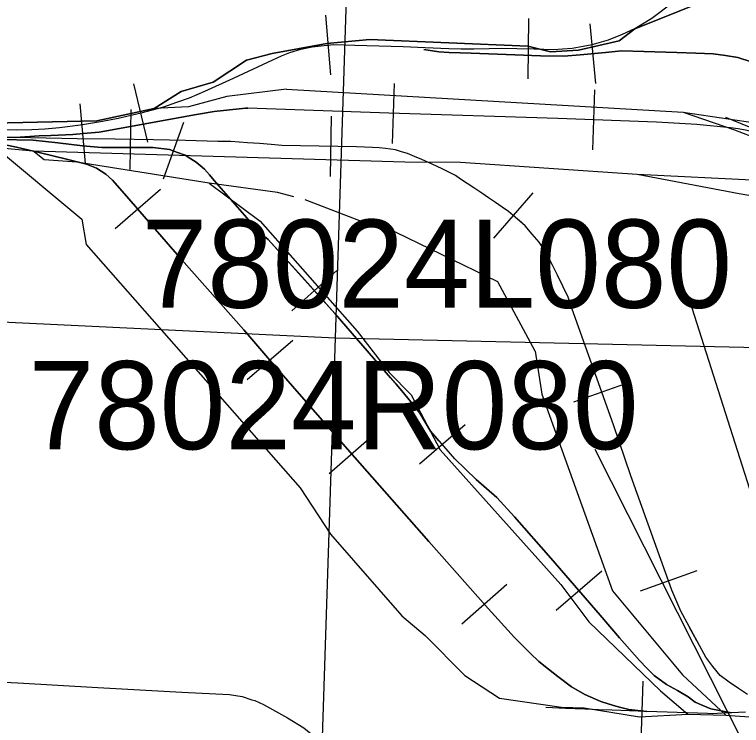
# Model space of a CAD drawing. Extents: x -132.8 to -73.3, y -60 to -26.
# Drawn here: x -124.287 to -123.38, y -50.739 to -49.852 of the extents above; entities that cross this region are included whole.
import ezdxf

# ---------------------------------------------------------------- set-up
doc = ezdxf.new("R2010")
doc.units = 0
for name, color, linetype in [('tdCoCityStreetMajor', 7, 'Continuous'), ('tdCoRRCL', 7, 'Continuous'), ('tdCoSectLine', 7, 'Continuous'), ('tdCoStrucPriMaintName', 7, 'Continuous')]:
    doc.layers.add(name, color=color, linetype=linetype)

msp = doc.modelspace()

# ---------------------------------------------------------------- linework, layer by layer
at = {"layer": 'tdCoCityStreetMajor'}
msp.add_lwpolyline([(-124.81065, -50.63822), (-124.79515, -50.64818), (-124.78487, -50.6531), (-124.78384, -50.6536), (-124.76904, -50.65769), (-124.75304, -50.65973), (-124.7185, -50.66154), (-124.65337, -50.66479), (-124.54813, -50.67104), (-124.45891, -50.67598), (-124.36561, -50.68127), (-124.28295, -50.68524), (-124.18296, -50.69102), (-124.07817, -50.69703), (-124.01897, -50.70004), (-124.00321, -50.70257), (-123.99084, -50.70644), (-123.98744, -50.7075), (-123.97662, -50.71255), (-123.9463, -50.72892), (-123.9262, -50.74143), (-123.91237, -50.75262), (-123.89428, -50.77269)], dxfattribs=at)
at = {"layer": 'tdCoRRCL'}
for p, q in [((-123.8924, -49.92708), (-123.89889, -49.85237)), ((-123.64625, -49.93176), (-123.64535, -49.85677)), ((-123.56938, -49.86305), (-123.56253, -49.93773)), ((-123.84368, -49.88279), (-123.89747, -49.88769)), ((-123.89747, -49.88769), (-123.84368, -49.88279)), ((-123.6466, -49.89112), (-123.84368, -49.88279)), ((-123.84368, -49.88279), (-123.6466, -49.89112)), ((-123.61837, -49.89816), (-123.6466, -49.89112)), ((-123.6466, -49.89112), (-123.61837, -49.89816)), ((-123.99746, -49.90873), (-124.03921, -49.93604)), ((-124.03921, -49.93604), (-123.99746, -49.90873)), ((-124.12083, -50.01086), (-124.13823, -49.93791)), ((-123.8135, -49.93758), (-123.81583, -50.01254)), ((-123.94789, -49.94475), (-123.45303, -49.97349)), ((-123.56344, -49.94558), (-123.56616, -50.02053)), ((-124.19849, -50.03762), (-124.20508, -49.96291)), ((-124.11267, -49.96882), (-124.1841, -49.98431)), ((-124.1841, -49.98431), (-124.11267, -49.96882)), ((-124.14191, -49.96999), (-124.14297, -50.04498)), ((-123.45303, -49.97349), (-123.36341, -49.98689)), ((-123.45303, -49.97349), (-123.38889, -49.99569)), ((-123.89205, -49.97861), (-123.89332, -50.0536)), ((-124.07616, -49.98652), (-124.10157, -50.05709)), ((-123.38889, -49.99569), (-123.33107, -50.01771)), ((-124.31123, -50.01726), (-124.26399, -50.02165)), ((-124.26399, -50.02165), (-123.80031, -50.03539)), ((-123.80031, -50.03539), (-123.73086, -50.03563)), ((-123.73086, -50.03563), (-123.51029, -50.05088)), ((-123.51029, -50.05088), (-123.22339, -50.06471)), ((-123.51029, -50.05088), (-123.38306, -50.07473)), ((-123.95914, -50.07382), (-124.04408, -50.06213)), ((-124.10476, -50.07007), (-124.16146, -50.11916)), ((-123.93877, -50.07909), (-123.95914, -50.07382)), ((-123.64058, -50.07394), (-123.68979, -50.13054)), ((-123.85433, -50.1097), (-123.92465, -50.08262)), ((-123.88514, -50.17114), (-123.94091, -50.22128)), ((-123.94002, -50.25836), (-123.99697, -50.30717)), ((-123.63758, -50.27158), (-123.62951, -50.32543)), ((-123.51935, -50.31012), (-123.59002, -50.33526)), ((-123.72507, -50.36358), (-123.78178, -50.41267)), ((-123.83809, -50.37519), (-123.89436, -50.42478)), ((-123.5545, -50.54596), (-123.61125, -50.59499)), ((-123.43613, -50.54579), (-123.50675, -50.57104)), ((-123.6728, -50.56275), (-123.72907, -50.61234)), ((-123.50316, -50.6834), (-123.50567, -50.75836)), ((-123.44736, -50.72464), (-123.40004, -50.72588)), ((-123.40004, -50.72588), (-123.31179, -50.73135))]:
    msp.add_line(p, q, dxfattribs=at)
for points in [[(-124.31163, -49.99527), (-124.28437, -49.99554), (-124.26524, -49.99501), (-124.24898, -49.99423), (-124.23063, -49.99239), (-124.20468, -49.98925), (-124.17716, -49.98479), (-124.15776, -49.98112), (-124.12918, -49.9743), (-124.10061, -49.9667), (-124.08436, -49.96093), (-124.06889, -49.95543), (-124.04949, -49.9473), (-124.01384, -49.93105), (-123.96482, -49.90798), (-123.95381, -49.903), (-123.94359, -49.89907), (-123.9297, -49.89487), (-123.9158, -49.89199), (-123.9006, -49.89016), (-123.88854, -49.88911), (-123.86259, -49.88989), (-123.80229, -49.89173), (-123.77475, -49.89274), (-123.74541, -49.89383), (-123.72994, -49.89461), (-123.71395, -49.89461), (-123.69508, -49.89383), (-123.67988, -49.89356), (-123.66048, -49.89409), (-123.63872, -49.89435), (-123.61486, -49.89514), (-123.60359, -49.89461), (-123.59153, -49.89356), (-123.57764, -49.8912), (-123.56663, -49.88885), (-123.54618, -49.88334), (-123.52862, -49.87626), (-123.51315, -49.86892), (-123.49218, -49.85634), (-123.46492, -49.83563)], [(-124.31163, -49.99527), (-124.28437, -49.99554), (-124.26524, -49.99501), (-124.24898, -49.99423), (-124.23063, -49.99239), (-124.20468, -49.98925), (-124.17716, -49.98479), (-124.15776, -49.98112), (-124.12918, -49.9743), (-124.10061, -49.9667), (-124.08436, -49.96093), (-124.06889, -49.95543), (-124.04949, -49.9473), (-124.01384, -49.93105), (-123.96482, -49.90798), (-123.95381, -49.903), (-123.94359, -49.89907), (-123.9297, -49.89487), (-123.9158, -49.89199), (-123.9006, -49.89016), (-123.88854, -49.88911), (-123.86259, -49.88989), (-123.80229, -49.89173), (-123.77475, -49.89274), (-123.74541, -49.89383), (-123.72994, -49.89461), (-123.71395, -49.89461), (-123.69508, -49.89383), (-123.67988, -49.89356), (-123.66048, -49.89409), (-123.63872, -49.89435), (-123.61486, -49.89514), (-123.60359, -49.89461), (-123.59153, -49.89356), (-123.57764, -49.8912), (-123.56663, -49.88885), (-123.54618, -49.88334), (-123.52862, -49.87626), (-123.51315, -49.86892), (-123.49218, -49.85634), (-123.46492, -49.83563)], [(-123.43529, -49.83828), (-123.51345, -49.86936), (-123.53279, -49.88463)], [(-123.53279, -49.88463), (-123.51345, -49.86936), (-123.43529, -49.83828)], [(-123.53279, -49.88463), (-123.58359, -49.89592), (-123.61837, -49.89816)], [(-123.61837, -49.89816), (-123.58359, -49.89592), (-123.53279, -49.88463)], [(-123.89747, -49.88769), (-123.96566, -49.9001), (-123.99746, -49.90873)], [(-123.99746, -49.90873), (-123.96566, -49.9001), (-123.89747, -49.88769)], [(-123.77636, -49.89529), (-123.75773, -49.89815), (-123.74489, -49.89894), (-123.71762, -49.89999), (-123.6631, -49.90182), (-123.63112, -49.90313), (-123.60202, -49.90366), (-123.58157, -49.90182), (-123.55012, -49.89894), (-123.52993, -49.8971), (-123.50214, -49.89763), (-123.46099, -49.8992), (-123.43713, -49.89972), (-123.41564, -49.90077), (-123.40043, -49.90261), (-123.38497, -49.90523), (-123.36845, -49.91047)], [(-123.36845, -49.91047), (-123.38497, -49.90523), (-123.40043, -49.90261), (-123.41564, -49.90077), (-123.43713, -49.89972), (-123.46099, -49.8992), (-123.50214, -49.89763), (-123.52993, -49.8971), (-123.55012, -49.89894), (-123.58157, -49.90182), (-123.60202, -49.90366), (-123.63112, -49.90313), (-123.6631, -49.90182), (-123.71762, -49.89999), (-123.74489, -49.89894), (-123.75773, -49.89815), (-123.77636, -49.89529)], [(-124.03921, -49.93604), (-124.07897, -49.94762), (-124.11267, -49.96882)], [(-124.11267, -49.96882), (-124.07897, -49.94762), (-124.03921, -49.93604)], [(-123.94789, -49.94475), (-124.02231, -49.95384), (-124.07, -49.96679), (-124.11267, -49.96882)], [(-123.99614, -49.96832), (-123.99877, -49.9686), (-124.03783, -49.9728), (-124.05985, -49.9762), (-124.08973, -49.98171), (-124.16051, -49.99455), (-124.18148, -49.99822), (-124.19642, -49.9998), (-124.21425, -50.00137), (-124.24151, -50.00268), (-124.25619, -50.00294), (-124.28582, -50.00517), (-124.31166, -50.00452), (-124.39608, -50.00385), (-124.4516, -50.00305)], [(-124.4516, -50.00305), (-124.39608, -50.00385), (-124.31166, -50.00452), (-124.28582, -50.00517), (-124.25619, -50.00294), (-124.24151, -50.00268), (-124.21425, -50.00137), (-124.19642, -49.9998), (-124.18148, -49.99822), (-124.16051, -49.99455), (-124.08973, -49.98171), (-124.05985, -49.9762), (-124.03783, -49.9728), (-123.99877, -49.9686), (-123.99614, -49.96832)], [(-123.07285, -50.0604), (-123.12281, -50.05616), (-123.15614, -50.04919), (-123.2223, -50.03535), (-123.22552, -50.03467), (-123.26481, -50.0259), (-123.30142, -50.018), (-123.33709, -50.00708), (-123.34774, -50.00384), (-123.37315, -49.99612), (-123.38466, -49.9944), (-123.39412, -49.99298), (-123.43606, -49.98878), (-123.48639, -49.9859), (-123.60933, -49.98145), (-123.8201, -49.97489), (-123.99614, -49.96832)], [(-123.07285, -50.0604), (-123.12281, -50.05616), (-123.15614, -50.04919), (-123.2223, -50.03535), (-123.22552, -50.03467), (-123.26481, -50.0259), (-123.30142, -50.018), (-123.33709, -50.00708), (-123.34774, -50.00384), (-123.37315, -49.99612), (-123.38466, -49.9944), (-123.39412, -49.99298), (-123.43606, -49.98878), (-123.48639, -49.9859), (-123.60933, -49.98145), (-123.8201, -49.97489), (-123.99614, -49.96832)], [(-124.1841, -49.98431), (-124.4431, -49.99014), (-124.50308, -49.99014)], [(-124.50308, -49.99014), (-124.4431, -49.99014), (-124.1841, -49.98431)], [(-123.32035, -50.01265), (-123.39995, -49.98026)], [(-124.34646, -50.00681), (-124.32956, -50.00919), (-124.31265, -50.01157), (-124.29863, -50.01432), (-124.2846, -50.01707), (-124.27045, -50.02035), (-124.25629, -50.02363), (-124.22038, -50.03254), (-124.19705, -50.03831), (-124.18473, -50.04329), (-124.17319, -50.05089), (-124.16454, -50.05823), (-124.14986, -50.07527), (-124.07882, -50.15732), (-124.00097, -50.24487), (-123.96849, -50.28276)], [(-123.96849, -50.28276), (-124.00097, -50.24487), (-124.07882, -50.15732), (-124.14986, -50.07527), (-124.16454, -50.05823), (-124.17319, -50.05089), (-124.18473, -50.04329), (-124.19705, -50.03831), (-124.22038, -50.03254), (-124.25629, -50.02363), (-124.27045, -50.02035), (-124.2846, -50.01707), (-124.29863, -50.01432), (-124.31265, -50.01157), (-124.32956, -50.00919), (-124.34646, -50.00681)], [(-124.30497, -50.00757), (-124.26348, -50.00833), (-124.23271, -50.01191), (-124.20194, -50.01549), (-124.17804, -50.01773), (-124.16087, -50.0176), (-124.1437, -50.01747), (-124.12876, -50.0176), (-124.11382, -50.01773), (-124.09363, -50.02009), (-124.0838, -50.02363), (-124.07397, -50.02717), (-124.06716, -50.03149), (-124.06034, -50.03582), (-124.05523, -50.04014), (-124.05012, -50.04447), (-124.04396, -50.05154), (-124.0378, -50.05862), (-124.00031, -50.10188), (-123.99507, -50.10791), (-123.98983, -50.11393), (-123.98354, -50.12036), (-123.97724, -50.12678), (-123.97057, -50.1322), (-123.92882, -50.17864), (-123.88707, -50.22508), (-123.8526, -50.26493), (-123.81812, -50.30477), (-123.81105, -50.3129), (-123.80397, -50.32103), (-123.79263, -50.33499), (-123.78129, -50.34895), (-123.77467, -50.36015), (-123.76806, -50.37136), (-123.75759, -50.38332), (-123.73789, -50.40608), (-123.71125, -50.43174), (-123.68548, -50.45419), (-123.66346, -50.47831), (-123.61811, -50.52969), (-123.55651, -50.60099), (-123.53239, -50.62904), (-123.50749, -50.65761), (-123.49857, -50.66705), (-123.48927, -50.67636), (-123.47387, -50.68726), (-123.46033, -50.69511), (-123.4468, -50.70297), (-123.43805, -50.70967), (-123.42835, -50.71374), (-123.41865, -50.7178), (-123.39271, -50.72278)], [(-123.39271, -50.72278), (-123.41865, -50.7178), (-123.42835, -50.71374), (-123.43805, -50.70967), (-123.4468, -50.70297), (-123.46033, -50.69511), (-123.47387, -50.68726), (-123.48927, -50.67636), (-123.49857, -50.66705), (-123.50749, -50.65761), (-123.53239, -50.62904), (-123.55651, -50.60099), (-123.61811, -50.52969), (-123.66346, -50.47831), (-123.68548, -50.45419), (-123.71125, -50.43174), (-123.73789, -50.40608), (-123.75759, -50.38332), (-123.76806, -50.37136), (-123.77467, -50.36015), (-123.78129, -50.34895), (-123.79263, -50.33499), (-123.80397, -50.32103), (-123.81105, -50.3129), (-123.81812, -50.30477), (-123.8526, -50.26493), (-123.88707, -50.22508), (-123.92882, -50.17864), (-123.97057, -50.1322), (-123.97724, -50.12678), (-123.98354, -50.12036), (-123.98983, -50.11393), (-123.99507, -50.10791), (-124.00031, -50.10188), (-124.0378, -50.05862), (-124.04396, -50.05154), (-124.05012, -50.04447), (-124.05523, -50.04014), (-124.06034, -50.03582), (-124.06716, -50.03149), (-124.07397, -50.02717), (-124.0838, -50.02363), (-124.09363, -50.02009), (-124.11382, -50.01773), (-124.12876, -50.0176), (-124.1437, -50.01747), (-124.16087, -50.0176), (-124.17804, -50.01773), (-124.20194, -50.01549), (-124.23271, -50.01191), (-124.26348, -50.00833), (-124.30497, -50.00757)], [(-123.37269, -50.70002), (-123.38419, -50.69262), (-123.39554, -50.68441), (-123.40688, -50.6762), (-123.41592, -50.66486), (-123.42497, -50.65352), (-123.45588, -50.5959), (-123.4674, -50.56972), (-123.5184, -50.42708), (-123.54011, -50.36365), (-123.59144, -50.21936), (-123.59666, -50.20421), (-123.60326, -50.19043), (-123.60987, -50.17664), (-123.61644, -50.16366), (-123.62302, -50.15067), (-123.62779, -50.14312), (-123.63256, -50.13556), (-123.64126, -50.12547), (-123.64995, -50.11539), (-123.65479, -50.11123), (-123.65964, -50.10706), (-123.66517, -50.10225), (-123.6707, -50.09744), (-123.67892, -50.09186), (-123.68714, -50.08627), (-123.69569, -50.08036), (-123.70424, -50.07444), (-123.71426, -50.06782), (-123.73058, -50.05688), (-123.73688, -50.05257), (-123.74519, -50.04842), (-123.75349, -50.04426), (-123.76629, -50.03831), (-123.77909, -50.03236), (-123.78796, -50.02877), (-123.79683, -50.02518), (-123.80424, -50.02282), (-123.81165, -50.02047), (-123.81793, -50.01957), (-123.82422, -50.01867), (-123.8323, -50.018), (-123.84038, -50.01732), (-123.85049, -50.01699), (-123.86059, -50.01665), (-123.90707, -50.01586), (-123.95354, -50.01508), (-123.96703, -50.01376), (-123.98121, -50.01238), (-123.9962, -50.01171), (-124.01708, -50.01014), (-124.03347, -50.00991), (-124.07355, -50.0089), (-124.11363, -50.00789), (-124.16123, -50.00722), (-124.20883, -50.00654), (-124.24732, -50.00586), (-124.28582, -50.00517)], [(-123.37269, -50.70002), (-123.38419, -50.69262), (-123.39554, -50.68441), (-123.40688, -50.6762), (-123.41592, -50.66486), (-123.42497, -50.65352), (-123.45588, -50.5959), (-123.4674, -50.56972), (-123.5184, -50.42708), (-123.54011, -50.36365), (-123.59144, -50.21936), (-123.59666, -50.20421), (-123.60326, -50.19043), (-123.60987, -50.17664), (-123.61644, -50.16366), (-123.62302, -50.15067), (-123.62779, -50.14312), (-123.63256, -50.13556), (-123.64126, -50.12547), (-123.64995, -50.11539), (-123.65479, -50.11123), (-123.65964, -50.10706), (-123.66517, -50.10225), (-123.6707, -50.09744), (-123.67892, -50.09186), (-123.68714, -50.08627), (-123.69569, -50.08036), (-123.70424, -50.07444), (-123.71426, -50.06782), (-123.73058, -50.05688), (-123.73688, -50.05257), (-123.74519, -50.04842), (-123.75349, -50.04426), (-123.76629, -50.03831), (-123.77909, -50.03236), (-123.78796, -50.02877), (-123.79683, -50.02518), (-123.80424, -50.02282), (-123.81165, -50.02047), (-123.81793, -50.01957), (-123.82422, -50.01867), (-123.8323, -50.018), (-123.84038, -50.01732), (-123.85049, -50.01699), (-123.86059, -50.01665), (-123.90707, -50.01586), (-123.95354, -50.01508), (-123.96703, -50.01376), (-123.98121, -50.01238), (-123.9962, -50.01171), (-124.01708, -50.01014), (-124.03347, -50.00991), (-124.07355, -50.0089), (-124.11363, -50.00789), (-124.16123, -50.00722), (-124.20883, -50.00654), (-124.24732, -50.00586), (-124.28582, -50.00517)], [(-124.31123, -50.01726), (-124.20308, -50.10687), (-124.19759, -50.13857), (-123.93087, -50.44217)], [(-124.04408, -50.06213), (-124.20911, -50.03571), (-124.25008, -50.03306), (-124.26399, -50.02165)], [(-124.04408, -50.06213), (-123.9806, -50.10954), (-123.85949, -50.24683), (-123.81979, -50.29836), (-123.7921, -50.32591), (-123.75601, -50.39469), (-123.60571, -50.56272), (-123.57062, -50.60939), (-123.48132, -50.69535), (-123.44736, -50.72464)], [(-123.38306, -50.07473), (-123.26522, -50.09517), (-123.25123, -50.10343)], [(-123.97057, -50.1322), (-123.97724, -50.12678), (-123.98983, -50.11393), (-124.00031, -50.10188)], [(-123.63758, -50.27158), (-123.68425, -50.18516), (-123.82453, -50.11679), (-123.85433, -50.1097)], [(-123.64995, -50.11539), (-123.65964, -50.10706)], [(-123.97057, -50.1322), (-123.88707, -50.22508), (-123.81812, -50.30477), (-123.80397, -50.32103), (-123.78129, -50.34895)], [(-123.96849, -50.28276), (-123.96322, -50.28891), (-123.87147, -50.39403), (-123.77028, -50.50885), (-123.69636, -50.59273), (-123.66359, -50.62865), (-123.64375, -50.64815), (-123.63292, -50.65879), (-123.62113, -50.6681), (-123.60933, -50.67741), (-123.59229, -50.69025), (-123.57578, -50.69995), (-123.55559, -50.7086), (-123.54642, -50.71162), (-123.53724, -50.71463), (-123.52898, -50.7166), (-123.52073, -50.71856), (-123.4982, -50.72109)], [(-123.4982, -50.72109), (-123.52073, -50.71856), (-123.52898, -50.7166), (-123.53724, -50.71463), (-123.54642, -50.71162), (-123.55559, -50.7086), (-123.57578, -50.69995), (-123.59229, -50.69025), (-123.60933, -50.67741), (-123.62113, -50.6681), (-123.63292, -50.65879), (-123.64375, -50.64815), (-123.66359, -50.62865), (-123.69636, -50.59273), (-123.77028, -50.50885), (-123.87147, -50.39403), (-123.96322, -50.28891), (-123.96849, -50.28276)], [(-123.62951, -50.32543), (-123.54121, -50.57072), (-123.45397, -50.67556), (-123.40004, -50.72588)], [(-123.76806, -50.37136), (-123.78129, -50.34895)], [(-123.75705, -50.38394), (-123.75759, -50.38332), (-123.76806, -50.37136)], [(-123.73789, -50.40608), (-123.75705, -50.38394)], [(-123.71125, -50.43174), (-123.73789, -50.40608)], [(-123.93087, -50.44217), (-123.89292, -50.49997), (-123.80403, -50.6017), (-123.77467, -50.62613), (-123.72547, -50.67633), (-123.68201, -50.70429), (-123.60497, -50.71578), (-123.57657, -50.71652)], [(-123.43614, -50.63313), (-123.44503, -50.6165)], [(-123.37514, -50.72199), (-123.38392, -50.72239), (-123.39271, -50.72278), (-123.40437, -50.72331), (-123.41603, -50.72383), (-123.42264, -50.72361), (-123.46042, -50.72235), (-123.4982, -50.72109), (-123.5199, -50.72036), (-123.5416, -50.71964), (-123.55869, -50.71893), (-123.57578, -50.71822), (-123.59998, -50.71723), (-123.62417, -50.71623)], [(-123.37514, -50.72199), (-123.38392, -50.72239), (-123.39271, -50.72278), (-123.40437, -50.72331), (-123.41603, -50.72383), (-123.42264, -50.72361), (-123.46042, -50.72235), (-123.4982, -50.72109), (-123.5199, -50.72036), (-123.5416, -50.71964), (-123.55869, -50.71893), (-123.57578, -50.71822), (-123.59998, -50.71723), (-123.62417, -50.71623)], [(-123.57657, -50.71652), (-123.50742, -50.7278), (-123.44736, -50.72464)]]:
    msp.add_lwpolyline(points, dxfattribs=at)
at = {"layer": 'tdCoSectLine'}
for points in [[(-123.88665, -50.25485), (-123.85393, -49.24233)], [(-124.8843, -50.20694), (-123.88665, -50.25485)], [(-123.91726, -51.20109), (-123.88665, -50.25485)], [(-123.88665, -50.25485), (-122.88642, -50.27774)]]:
    msp.add_lwpolyline(points, dxfattribs=at)
at = {"layer": 'tdCoStrucPriMaintName'}
for p, q in [((-123.44243, -50.21752), (-123.12655, -51.21019)), ((-123.44243, -50.21752), (-123.12655, -51.21019)), ((-123.44243, -50.21752), (-123.12655, -51.21019)), ((-123.56327, -50.39399), (-123.14868, -51.21388)), ((-123.56327, -50.39399), (-123.14868, -51.21388)), ((-123.56327, -50.39399), (-123.14868, -51.21388))]:
    msp.add_line(p, q, dxfattribs=at)

# ---------------------------------------------------------------- texts
for s, p in [('78024L080', (-124.1284, -50.21752)), ('78024L080', (-124.1284, -50.21752)), ('78024L080', (-124.1284, -50.21752)), ('78024R080', (-124.2694, -50.39399)), ('78024R080', (-124.2694, -50.39399)), ('78024R080', (-124.2694, -50.39399))]:
    msp.add_text(s, height=0.11, dxfattribs=at).set_placement(p)

doc.saveas('drawing.dxf')
